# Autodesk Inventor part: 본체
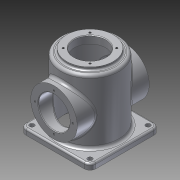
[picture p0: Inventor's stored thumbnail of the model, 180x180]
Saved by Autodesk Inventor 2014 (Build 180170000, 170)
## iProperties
Created: 2015-10
Part Number: 본체
Material: 알루미늄 6061
Document SubType Name: Modeling
Designer: USER
Density: 2.71 g/cm^3
Appearance: 알루미늄 - 평지
Mass: 982.687 g
Surface Area: 1041.97 cm^2
Volume: 362.615 cm^3
Author: USER
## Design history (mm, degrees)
sketch "스케치1"
  geometry: C1 r 50 at (0, 0); 1 further point
  constraints: 1 centre point, 1 coincident
  dimensions: "d0" = 100 diameter of C1
extrude "돌출1" new body sketch "스케치1" distance "d1" = 120; taper "d2" = 0 deg
sketch "스케치2"
  geometry: C1 r 50 at (0, 0) reference; C2 r 40 at (0, 0)
  constraints: 1 centre point, 1 coincident
  dimensions: "d3" = 80 diameter of C2
extrude "돌출2" join sketch "스케치2" distance "d4" = 5; taper "d5" = 0 deg
sketch "스케치3"
  geometry: C1 r 40 at (0, 0) reference; C2 r 27 at (0, 0)
  constraints: 1 centre point, 1 coincident
  dimensions: "d6" = 54 diameter of C2
extrude "돌출3" cut sketch "스케치3" distance "d7" = 13; taper "d8" = 0 deg
sketch "스케치4"
  geometry: C1 r 27 at (0, 0) reference; C2 r 45 at (0, 0)
  constraints: 1 centre point, 1 coincident
  dimensions: "d9" = 90 diameter of C2
extrude "돌출4" cut sketch "스케치4" distance "d10" = 112; taper "d11" = 0 deg
sketch "스케치5"
  geometry: L1 (-60, 60)-(60, 60); L2 (60, 60)-(60, -60); L3 (60, -60)-(-60, -60); L4 (-60, -60)-(-60, 60); C1 r 45 at (0, 0) reference; 2 further points
  constraints: 8 end point, 2 midpoint, 2 parallel, 1 horizontal, 1 horizontal alignment, 1 perpendicular, 1 vertical alignment
  dimensions: "d12" = 120 distance of L1.start L1.end; "d13" = 120 distance of L3.end L1.start
extrude "돌출5" join sketch "스케치5" distance "d14" = 10; taper "d15" = 0 deg
sketch "스케치6"
  geometry: L1 (0, 0)-(0, 32.5); L2 (0, 0)-(22.981, 22.981); C1 r 27 at (0, 0) reference; C2 r 40 at (0, 0) reference; A1 r 32.5 centre (0, 0) between (0, 32.5) and (22.981, 22.981); 1 further point
  constraints: 4 end point, 3 coincident, 2 point on circle, 1 centre point, 1 vertical
  dimensions: "d16" = 65 diameter of A1; "d17" = 45 deg angle of L2 L1
hole "구멍1" sketch "스케치6" at (22.981, 22.981) diameter "d18" = 3.459; stored, may be unused: countersink angle "d22" = 90 deg, drill point angle "d24" = 118 deg; dims "d19" = 8, "d20" = 4, "d21" = 2, "d23" = 10
sketch "스케치7"
  geometry: C1 r 50 at (0, 0) reference; C2 r 4 at (-50, 50); C3 r 4 at (50, 50); C4 r 4 at (50, -50); C5 r 4 at (-50, -50)
  constraints: 4 centre point
  dimensions: "d28" = 8 diameter of C2; "d29" = 8 diameter of C3; "d30" = 8 diameter of C4; "d31" = 8 diameter of C5; "d32" = 50 horizontal distance of C1.centre C2.centre; "d33" = 50 horizontal distance of C1.centre C3.centre; "d34" = 50 horizontal distance of C5.centre C1.centre; "d35" = 50 horizontal distance of C4.centre C1.centre; "d36" = 50 horizontal distance of C1.centre C2.centre; "d37" = 50 horizontal distance of C1.centre C3.centre; "d38" = 50 horizontal distance of C4.centre C1.centre; "d39" = 50 horizontal distance of C5.centre C1.centre
extrude "돌출6" cut sketch "스케치7" stored distance "d40" = 10; taper "d41" = 0 deg
fillet "모깎기1" dims "d42" = 10
node "작업 평면1"
sketch "스케치8"
  geometry: L1 (45, 0)-(-45, 0) reference; C1 r 40 at (0, 60); 2 further points
  constraints: 1 centre point, 1 midpoint, 1 vertical alignment
  dimensions: "d44" = 80 diameter of C1; "d45" = 60 distance from line of L1 C1.centre
extrude "돌출7" join sketch "스케치8" stored distance "d46" = 10; taper "d47" = 0 deg
fillet "모깎기2" dims "d48" = 3
fillet "모깎기4" dims "d50" = 5
sketch "스케치9"
  geometry: C1 r 40 at (0, 0) reference; C2 r 27 at (0, 0); 1 further point
  constraints: 1 centre point, 1 coincident
  dimensions: "d51" = 54 diameter of C2
extrude "돌출8" cut sketch "스케치9" stored distance "d52" = 10; taper "d53" = 0 deg
fillet "모깎기5" dims "d54" = 3
sketch "스케치10" dims "d55" = 65
  geometry: L1 (0, 0)-(0, 32.5); C1 r 40 at (0, 0) reference; 2 further points
  constraints: 2 coincident, 2 end point, 1 vertical, 1 vertical alignment, 2 other
hole "구멍2" sketch "스케치10" at (0, 32.5) diameter "d56" = 3.242; stored, may be unused: countersink angle "d60" = 90 deg, drill point angle "d62" = 118 deg; dims "d57" = 8, "d58" = 4, "d59" = 2, "d61" = 10
chamfer "모따기1" distance "d66" = 1; stored, may be unused: second distance "d67" = 2, angle "d68" = 45 deg
chamfer "모따기2" distance "d69" = 3; stored, may be unused: second distance "d70" = 2, angle "d71" = 45 deg
fillet "모깎기6" dims "d72" = 3
chamfer "모따기3" distance "d73" = 1; stored, may be unused: second distance "d74" = 2, angle "d75" = 45 deg
fillet "모깎기7" dims "d76" = 5
fillet "모깎기8" dims "d77" = 3
node "작업 평면5"
sketch "스케치13"
  geometry: 2 further points
  constraints: 1 vertical alignment, 1 other
  dimensions: "d83" = 70 distance of point (0, 0) point (0, 70)
feature "엠보싱1" sketch "스케치13" dims "d84" = 0.5, "d85" = 0
fillet "모깎기9" dims "d86" = 5
node "솔리드1"
pattern_circular "원형 패턴1" dims angle "d26" = 360 deg
pattern_circular "원형 패턴2" dims angle "d64" = 360 deg
mirror "대칭1"
node "작업 평면2"
other parameters: "d43" = 62
